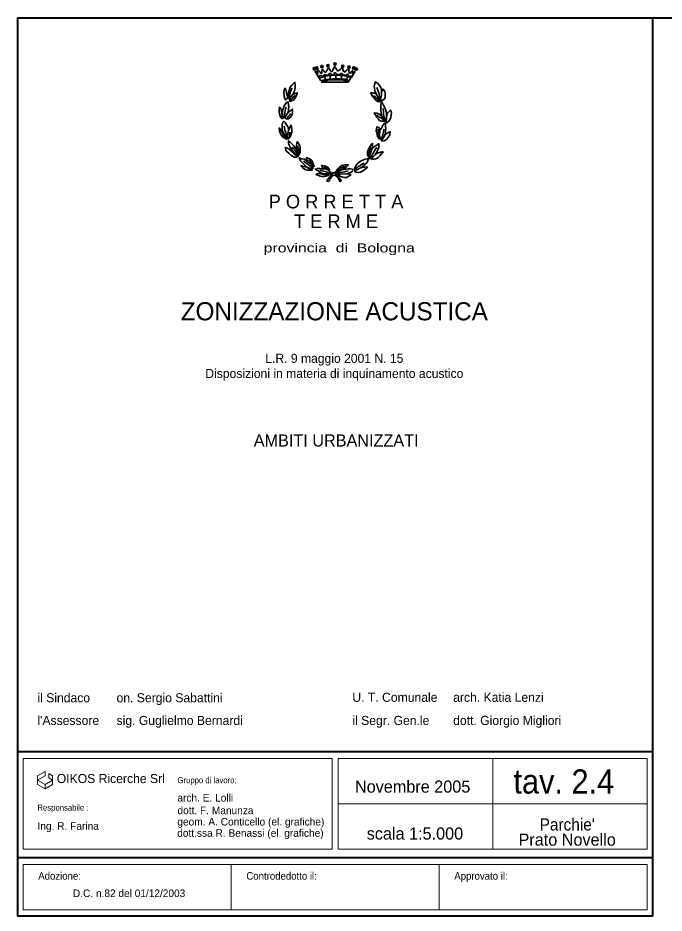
# Model space of a CAD drawing. Extents: x 650071 to 653841, y 889105 to 891996.
# Drawn here: x 650071 to 651141, y 890515 to 891996 of the extents above; entities that cross this region are included whole.
import ezdxf
from ezdxf.enums import TextEntityAlignment as Align

# ---------------------------------------------------------------- set-up
doc = ezdxf.new("R2010")
doc.units = 0
doc.header["$LTSCALE"] = 5.6
doc.layers.add('61', color=7, linetype='Continuous', lineweight=35)

msp = doc.modelspace()

# ---------------------------------------------------------------- hatches: boundary and pattern name
at = {"layer": '61'}
for points in [[(650596.16, 891921.2, 1), (650596.16, 891917.36, 1)], [(650561.94, 891913.61, 1), (650561.94, 891909.77, 1)], [(650566.08, 891914.72, 1), (650566.08, 891910.88, 1)], [(650574.52, 891917.09, 1), (650574.52, 891913.25, 1)], [(650584.49, 891918.36, 1), (650584.49, 891914.51, 1)], [(650608.89, 891917.57, 1), (650608.89, 891913.72, 1)], [(650619.17, 891916.46, 1), (650619.17, 891912.61, 1)], [(650627.3, 891914.72, 1), (650627.3, 891910.88, 1)], [(650631.29, 891913.3, 1), (650631.29, 891909.45, 1)]]:
    msp.add_hatch(color=256, dxfattribs=at).paths.add_polyline_path(points)

# ---------------------------------------------------------------- linework, layer by layer
at = {"layer": '61', "lineweight": 40}
for p, q in [((651121.43, 891995.66), (652174.45, 891995.66)), ((650071.44, 890782.2), (651121.44, 890782.2)), ((650071.44, 890606.7), (651121.44, 890606.7))]:
    msp.add_line(p, q, dxfattribs=at)
at = {"layer": '61'}
for p, q in [((650581.11, 891893.8), (650578.36, 891898.72)), ((650585.86, 891901.37), (650585.86, 891901.25)), ((650588.49, 891894.77), (650587.86, 891900.45)), ((650597.51, 891895.4), (650597.51, 891900.77)), ((650607.06, 891894.92), (650607.21, 891900.77)), ((650615.34, 891893.32), (650616.71, 891898.4)), ((650508.59, 891832.05), (650508.29, 891828.72)), ((650537.44, 891770.77), (650534.84, 891773.15)), ((650534.53, 891766.35), (650537.43, 891770.78)), ((650587.86, 891743.6), (650585.56, 891743.12)), ((650572.98, 891739.49), (650570.21, 891738.53))]:
    msp.add_line(p, q, dxfattribs=at)
at = {"layer": '61', "lineweight": 13}
for p, q in [((650079.96, 890770.65), (650079.96, 890620.22)), ((650079.96, 890770.65), (650591.41, 890770.65)), ((650591.41, 890770.65), (650591.41, 890620.22)), ((650601.44, 890770.65), (650601.44, 890620.22)), ((650601.44, 890770.65), (651112.91, 890770.65)), ((650857.19, 890770.65), (650857.19, 890620.22)), ((651112.91, 890770.65), (651112.91, 890620.22)), ((650601.42, 890695.44), (651112.9, 890695.44)), ((650079.96, 890620.22), (650591.41, 890620.22)), ((650601.44, 890620.22), (651112.91, 890620.22)), ((650079.96, 890595.17), (651112.91, 890595.17)), ((650079.96, 890595.15), (650079.96, 890519.95)), ((650424.26, 890595.15), (650424.26, 890519.95)), ((650768.59, 890595.15), (650768.59, 890519.95)), ((651112.91, 890595.15), (651112.91, 890519.95)), ((650079.96, 890519.95), (651112.91, 890519.95))]:
    msp.add_line(p, q, dxfattribs=at)
at = {"layer": '61', "lineweight": 40}
msp.add_lwpolyline([(651121.44, 891995.65), (651121.44, 890509.4), (650071.44, 890509.4), (650071.44, 891995.65)], close=True, dxfattribs=at)
at = {"layer": '61'}
for points in [[(650585.24, 891913.1), (650584.04, 891911.05), (650581.71, 891906.62), (650580.79, 891905.67), (650579.59, 891905.67), (650578.96, 891906.45), (650578.04, 891907.4), (650577.14, 891908.82), (650574.99, 891910.4), (650574.66, 891907.72), (650574.51, 891905.67), (650574.36, 891904.4), (650572.84, 891904.07), (650571.46, 891906), (650569.44, 891907.87), (650567.31, 891909.8), (650567.49, 891907.25), (650567.76, 891904.72), (650567.61, 891903.3), (650565.16, 891906.92), (650563.76, 891907.87), (650562.54, 891907.72)], [(650562.54, 891907.72), (650567.61, 891899.65), (650569.31, 891896.97), (650570.24, 891897.62), (650570.39, 891898.1), (650570.06, 891899.17), (650570.39, 891899.97), (650570.99, 891900.62), (650572.84, 891900.45), (650573.76, 891899.65), (650574.06, 891898.52), (650577.44, 891899.82), (650577.44, 891900.3), (650577.44, 891900.77), (650577.74, 891901.07), (650578.36, 891901.55), (650578.66, 891901.72), (650579.59, 891901.72), (650580.19, 891901.37), (650580.79, 891900.77), (650585.86, 891901.25)], [(650629.46, 891907.25), (650628.54, 891907.25), (650627.46, 891906.62), (650627.14, 891905.02), (650626.84, 891903.15), (650625.94, 891901.72), (650625.14, 891902.5), (650625.01, 891904.25), (650625.31, 891906.92), (650625.01, 891908.82), (650622.39, 891906), (650621.01, 891904.4), (650620.39, 891904.25), (650619.94, 891904.25), (650619.64, 891905.2), (650619.16, 891907.87), (650619.16, 891910.4), (650617.94, 891911.22), (650615.64, 891909.3), (650613.66, 891907.57), (650612.86, 891906.45), (650611.64, 891906), (650610.59, 891906.77), (650609.79, 891908.67), (650608.59, 891912.32), (650607.36, 891912.95), (650604.59, 891910.4), (650602.29, 891908.52), (650601.06, 891907.87), (650600.29, 891907.87), (650599.06, 891909.8), (650597.51, 891912.62), (650595.84, 891915), (650593.99, 891912.8), (650592.46, 891909.17), (650591.54, 891907.25), (650590.16, 891906.92), (650588.94, 891908.05), (650586.94, 891911.05), (650585.24, 891913.1)], [(650585.86, 891901.37), (650585.86, 891901.87), (650585.86, 891902.5), (650586.16, 891903), (650586.94, 891903.47), (650587.86, 891903.62), (650588.79, 891903.47), (650589.71, 891903), (650589.71, 891901.72), (650594.61, 891901.72), (650594.61, 891902.17), (650594.61, 891903.62), (650594.79, 891904.25), (650595.54, 891904.55), (650596.61, 891904.87), (650597.69, 891904.25), (650598.61, 891903.3), (650598.61, 891902.35), (650605.04, 891901.87), (650605.04, 891902.17), (650605.04, 891902.67), (650605.34, 891903.47), (650605.84, 891903.77), (650606.89, 891903.77), (650607.96, 891903.47), (650608.59, 891902.02), (650614.86, 891900.62), (650614.86, 891901.25), (650615.49, 891902.02), (650616.26, 891902.67), (650617.49, 891902.67), (650617.94, 891901.55), (650617.94, 891899.82), (650621.46, 891898.85), (650621.64, 891899.5), (650622.56, 891899.97), (650623.76, 891898.52), (650623.31, 891897.3), (650626.84, 891902.35), (650629.46, 891907.25)], [(650519.49, 891872.52), (650520.86, 891877.42), (650522.24, 891881.25), (650524.71, 891884.52), (650527.31, 891887.07), (650529.76, 891889), (650530.54, 891885.17), (650530.54, 891880.6), (650529.61, 891876.47), (650528.24, 891872.52), (650526.41, 891868.72), (650528.84, 891870.17), (650533.46, 891871.9), (650533.31, 891870.45), (650532.06, 891866.37), (650530.54, 891863.35), (650527.79, 891860.35), (650524.39, 891858.62), (650521.34, 891857.5), (650520.71, 891861.62)], [(650520.56, 891861.62), (650520.56, 891865.25), (650521.19, 891869.05), (650522.24, 891872.37), (650523.34, 891875.37), (650525.16, 891879.32)], [(650671.19, 891860.12), (650669.66, 891864.32), (650669.04, 891869.22), (650668.14, 891873.02), (650666.91, 891876.02), (650665.51, 891880.6)], [(650520.56, 891861.62), (650519.19, 891864.65), (650518.89, 891868.1), (650519.49, 891872.52)], [(650526.41, 891868.72), (650523.19, 891865.07), (650520.71, 891861.62)], [(650521.34, 891857.5), (650523.64, 891861.15), (650525.31, 891862.55), (650527.31, 891865.25), (650530.06, 891867.47)], [(650664.29, 891869.85), (650666.29, 891865.75), (650668.44, 891862.6), (650669.49, 891860.2), (650670.56, 891858.15), (650667.51, 891859.72), (650665.69, 891861.62), (650663.84, 891863.67), (650661.66, 891866.05), (650660.46, 891867.5)], [(650673.34, 891873.17), (650673.04, 891868.6), (650672.59, 891864.95), (650671.81, 891862.12), (650670.56, 891858.15)], [(650508.29, 891828.72), (650511.36, 891832.05), (650512.61, 891834.72), (650512.89, 891838.85), (650513.96, 891842.32), (650514.44, 891845.17), (650515.19, 891848.02)], [(650517.19, 891836.8), (650515.04, 891833.62), (650513.36, 891830.62)], [(650515.19, 891828.42), (650517.34, 891831.1), (650519.01, 891833), (650521.34, 891835.52), (650522.56, 891837.45)], [(650675.94, 891827.82), (650673.19, 891829.55), (650669.49, 891831.27), (650665.19, 891834.92)], [(650678.39, 891825.1), (650675.94, 891827.82), (650675.16, 891830.17), (650673.49, 891833.35)], [(650682.21, 891821.62), (650679.31, 891826.37), (650677.46, 891831.57), (650676.71, 891836.05), (650676.24, 891840.3), (650675.64, 891845.97)], [(650519.01, 891795.4), (650521.94, 891798.57), (650523.16, 891801.72), (650524.71, 891807.12), (650524.56, 891810.87), (650524.09, 891815.65), (650523.16, 891818.32), (650520.86, 891812.8), (650519.49, 891809.8), (650518.74, 891805.7), (650519.01, 891811.7), (650518.09, 891815.8), (650515.81, 891818.97), (650513.51, 891822.6), (650511.66, 891824.82), (650509.84, 891822.92), (650508.59, 891818.5), (650508.59, 891815.65), (650508.59, 891811.52), (650509.51, 891808.05), (650511.96, 891803.3), (650514.56, 891799.2), (650515.81, 891795.25), (650515.04, 891796.82), (650513.34, 891798.72), (650511.19, 891801.72), (650509.36, 891805.2), (650507.84, 891809), (650503.84, 891813.75), (650504.29, 891808.52), (650505.39, 891805.5), (650506.31, 891802.97), (650508.44, 891800.3), (650510.11, 891798.25), (650512.89, 891796.67), (650515.81, 891795.25), (650519.02, 891795.41)], [(650516.11, 891797.7), (650515.66, 891800.77), (650514.74, 891805.82), (650513.04, 891809.95), (650512.61, 891813.27), (650511.96, 891816.77)], [(650681.46, 891831.27), (650681.16, 891828.57), (650680.84, 891827.17), (650682.21, 891821.62)], [(650518.74, 891805.7), (650517.79, 891801.42), (650517.19, 891798.57), (650515.04, 891796.82)], [(650517.19, 891798.57), (650519.01, 891795.4), (650520.11, 891798.72), (650521.46, 891802.82), (650521.64, 891806.62)], [(650669.44, 891795.72), (650668.89, 891799.52), (650668.14, 891805.05), (650667.51, 891808.67), (650667.51, 891811.37)], [(650670.56, 891809.97), (650670.26, 891806.8), (650669.96, 891803.95), (650669.96, 891801.72), (650670.56, 891798.57)], [(650678.56, 891802.2), (650676.86, 891798.4), (650673.51, 891793.65), (650673.64, 891797.45), (650674.56, 891800.77), (650675.64, 891804.72), (650676.41, 891807.9), (650677.31, 891811.7)], [(650537.44, 891770.77), (650538.49, 891772.97), (650538.79, 891775.17), (650538.79, 891777.7), (650538.66, 891780.87), (650538.19, 891784.05), (650537.11, 891786.25), (650535.26, 891788.77), (650533.59, 891791.15), (650532.81, 891788.77), (650532.51, 891784.52), (650532.39, 891781.85), (650532.81, 891778.02), (650530.21, 891780.42), (650528.06, 891784.2), (650525.16, 891787.05), (650521.79, 891789.9), (650519.01, 891792.12), (650519.01, 891790.52), (650519.19, 891788.15), (650520.39, 891785), (650522.09, 891781.67), (650523.94, 891778.35), (650526.21, 891775.02), (650528.39, 891772.32), (650531.89, 891769.65), (650534.51, 891766.35), (650533.59, 891767.45), (650530.36, 891769), (650527.44, 891771.25), (650525.16, 891773.77), (650522.86, 891775.97), (650520.71, 891778.35), (650517.01, 891780.07), (650513.81, 891781.05), (650514.89, 891776.92), (650516.71, 891774.4), (650520.11, 891771.4), (650522.86, 891768.55), (650525.76, 891766.65)], [(650532.81, 891778.02), (650534.84, 891773.15), (650534.84, 891769), (650533.59, 891767.45), (650532.99, 891772.32), (650530.96, 891775.17), (650528.99, 891777.55), (650526.84, 891779.77), (650525.49, 891781.67)], [(650537.44, 891770.77), (650535.89, 891774.7), (650535.59, 891779), (650534.84, 891783.9)], [(650653.56, 891764.42), (650651.71, 891769.17), (650652.81, 891772.65), (650653.89, 891778.52), (650655.24, 891780.72), (650656.01, 891782)], [(650658.16, 891780.42), (650657.09, 891778.52), (650656.16, 891775.17), (650655.56, 891773.77), (650654.49, 891770.12), (650653.56, 891767.27), (650653.56, 891764.42)], [(650654.34, 891762.87), (650656.46, 891766.5), (650658.61, 891770.77), (650661.39, 891775.67), (650663.84, 891779.62), (650666.16, 891780.72)], [(650525.76, 891766.65), (650528.84, 891765.52), (650532.06, 891765.37), (650534.51, 891766.35)], [(650559.99, 891746.42), (650557.21, 891748.95), (650554.76, 891750.82), (650552.46, 891752.45), (650550.31, 891754.17), (650548.01, 891755.9), (650546.01, 891757), (650544.16, 891758.42)], [(650561.81, 891749.27), (650561.21, 891751.62), (650560.29, 891753.85), (650559.36, 891756.37), (650558.29, 891758.62), (650557.04, 891760.5), (650555.21, 891762.07), (650551.99, 891763.35), (650549.09, 891764.45), (650549.24, 891763.5), (650549.84, 891760.97), (650550.46, 891758.3)], [(650550.47, 891758.31), (650556.61, 891752.91), (650557.45, 891751.73), (650559.98, 891750.71), (650561.82, 891749.28)], [(650561.81, 891749.27), (650558.89, 891753.07), (650556.91, 891755.6), (650555.21, 891758.42), (650553.69, 891760.02), (650552.59, 891760.5)], [(650654.34, 891762.87), (650657.54, 891764.75), (650660.01, 891766.35)], [(650561.81, 891749.27), (650559.99, 891750.7), (650557.46, 891751.72)], [(650589.71, 891740.1), (650586.79, 891742.17), (650584.34, 891744.05), (650580.79, 891745.32), (650577.59, 891745.8), (650574.21, 891746.12), (650570.84, 891746.42), (650567.61, 891746.25), (650564.71, 891745.65), (650563.46, 891745.5), (650564.86, 891744.22), (650566.99, 891743.42), (650568.69, 891742.62), (650570.99, 891740.87), (650572.96, 891739.47)], [(650589.71, 891740.1), (650585.86, 891739.77), (650583.56, 891739.97), (650581.44, 891740.87), (650579.11, 891741.7), (650576.51, 891742.17), (650574.06, 891743.12), (650571.46, 891743.25)], [(650587.86, 891743.6), (650586.04, 891746.12), (650583.89, 891748.65), (650581.44, 891750.07), (650578.04, 891750.85), (650574.81, 891751.65), (650573.89, 891751.95), (650574.66, 891750.22), (650576.21, 891747.7), (650578.04, 891747.22), (650580.04, 891747.07), (650582.56, 891744.7)], [(650586.74, 891743.35), (650583.74, 891746.42), (650581.11, 891748.17), (650578.04, 891749.75)], [(650582.56, 891744.71), (650584.35, 891744.07), (650585.57, 891743.12), (650587.86, 891743.61)], [(650596.46, 891738.67), (650601.21, 891742.8), (650603.81, 891745.15), (650606.89, 891747.37), (650610.41, 891749.27), (650613.66, 891749.75)], [(650596.76, 891735.5), (650601.39, 891738.85), (650604.74, 891739.77), (650609.19, 891740.4), (650612.14, 891741.2), (650615.94, 891742.17), (650617.79, 891742.5)], [(650607.36, 891744.05), (650604.59, 891743.12), (650602.44, 891741.52), (650600.14, 891739.97), (650599.06, 891738.35), (650596.91, 891736.77)], [(650628.29, 891745.15), (650631.99, 891747.2), (650634.56, 891749.72), (650637.49, 891750.7), (650639.94, 891753.22), (650644.26, 891755.12)], [(650639.11, 891747.57), (650636.26, 891746.42), (650634.44, 891745.3), (650632.41, 891744.35), (650631.19, 891743.57), (650630.29, 891742.92), (650629.21, 891742)], [(650570.21, 891738.52), (650568.21, 891738.05), (650566.09, 891736.95), (650564.86, 891736.62), (650566.99, 891735.67), (650569.44, 891734.72), (650571.76, 891733.95), (650574.51, 891733.47), (650576.66, 891733.3), (650578.81, 891733.47), (650581.29, 891733.95), (650584.19, 891734.72), (650586.94, 891736), (650582.34, 891737.87), (650584.49, 891738.05), (650588.01, 891738.35), (650589.71, 891740.1)], [(650570.21, 891738.52), (650572.66, 891737.57), (650574.99, 891737.1), (650577.44, 891736.47), (650580.64, 891736.15), (650584.04, 891736.15), (650586.94, 891736)], [(650582.34, 891737.87), (650578.51, 891737.87), (650575.44, 891738.35), (650572.96, 891739.47)], [(650593.56, 891739.77), (650592.64, 891738.35), (650591.84, 891737.1), (650591.54, 891734.87)], [(650596.76, 891735.5), (650601.99, 891736.77), (650607.36, 891737.42), (650612.74, 891737.1), (650615.49, 891737.72)]]:
    msp.add_lwpolyline(points, dxfattribs=at)
for points in [[(650572.84, 891891.6), (650570.24, 891895.85), (650573.76, 891897.12), (650578.36, 891898.72), (650584.19, 891899.82), (650591.09, 891900.62), (650598.31, 891900.77), (650604.44, 891900.62), (650609.36, 891900.3), (650613.96, 891899.35), (650618.26, 891897.92), (650622.56, 891896.32), (650619.16, 891890.95), (650617.31, 891892.85), (650612.74, 891894.12), (650604.31, 891894.92), (650599.21, 891895.4), (650593.06, 891894.92), (650586.16, 891894.27), (650581.11, 891893.8), (650576.51, 891892.7)], [(650577.89, 891890.95), (650584.81, 891892.4), (650591.09, 891893), (650597.51, 891893.47), (650602.59, 891893.32), (650609.96, 891892.55), (650615.34, 891891.75), (650618.16, 891889.6), (650574.29, 891889.3)], [(650514.56, 891877.42), (650515.36, 891875.22), (650516.11, 891871.57), (650517.04, 891867.8), (650517.34, 891864.92), (650516.86, 891862.1), (650514.44, 891860.02), (650513.36, 891862.4), (650512.29, 891865.57), (650511.79, 891868.4), (650511.51, 891872.05), (650511.79, 891875.85), (650512.89, 891879), (650513.36, 891879.65)], [(650669.36, 891856.72), (650670.56, 891858.15), (650675.19, 891859.57), (650677.16, 891860.5), (650679.04, 891863.52), (650679.19, 891866.67), (650679.19, 891871.42), (650678.39, 891873.35), (650677.34, 891876.32), (650675.19, 891878.07), (650674.74, 891876.2), (650673.34, 891873.17), (650673.04, 891876.32), (650671.81, 891880.6), (650669.66, 891884.1), (650667.51, 891886.45), (650663.36, 891889.95), (650662.59, 891888.82), (650661.36, 891885.2), (650661.24, 891882.82), (650661.36, 891879.5), (650661.99, 891876.32), (650662.76, 891873.67), (650664.29, 891869.85), (650661.06, 891871.42), (650657.86, 891871.57), (650655.39, 891871.75), (650657.39, 891867.65), (650659.39, 891864.47), (650661.36, 891862.12), (650663.84, 891859.72), (650666.61, 891857.52)], [(650508.29, 891828.72), (650505.69, 891833.15), (650504.59, 891836.95), (650503.69, 891840.6), (650503.69, 891844.37), (650504.59, 891848.02), (650507.51, 891843.9), (650507.84, 891841.37), (650507.99, 891836.95), (650508.59, 891832.05), (650509.21, 891836.47), (650509.21, 891839.65), (650509.96, 891844.37), (650510.76, 891846.27), (650511.66, 891848.82), (650512.89, 891851.67), (650514.29, 891853.57), (650516.56, 891856.1), (650518.26, 891856.87), (650519.01, 891852.92), (650519.64, 891848.17), (650519.19, 891844.05), (650518.41, 891839.97), (650517.19, 891836.8), (650519.34, 891839), (650521.64, 891841.52), (650524.56, 891843.6), (650525.64, 891844.87), (650525.64, 891841.22), (650525.64, 891837.75), (650525.01, 891835.2), (650523.46, 891833), (650521.49, 891830.45), (650519.49, 891828.9), (650517.19, 891828.42), (650515.19, 891828.42), (650513.36, 891830.62)], [(650678.39, 891825.1), (650673.64, 891824.97), (650670.09, 891826.2), (650667.64, 891828.57), (650665.64, 891830.65), (650664.11, 891833.5), (650661.96, 891836.82), (650661.04, 891838.87), (650665.34, 891838.25), (650668.89, 891836.97), (650673.49, 891833.35), (650672.69, 891837.92), (650671.94, 891842.35), (650671.79, 891845.52), (650671.79, 891852.65), (650672.86, 891858.17), (650674.71, 891854.52), (650677.16, 891850.1), (650679.46, 891845.82), (650681.46, 891839.17), (650681.46, 891831.27), (650682.06, 891833.5), (650682.69, 891837.45), (650685.14, 891840.45), (650686.81, 891842.02), (650688.06, 891843.15), (650688.99, 891840.92), (650689.44, 891838.07), (650689.29, 891835.07), (650688.51, 891830.97), (650686.81, 891827.17), (650684.54, 891824.17), (650682.21, 891821.62)], [(650670.41, 891794.27), (650668.44, 891797.15), (650666.74, 891799.05), (650665.69, 891802.05), (650665.19, 891805.82), (650664.44, 891808.05), (650664.74, 891812.65), (650665.36, 891815.17), (650668.14, 891814.7), (650669.81, 891812.65), (650670.56, 891809.97), (650672.86, 891813.27), (650675.64, 891818.5), (650678.09, 891821.5), (650679.49, 891820.72), (650679.79, 891817.37), (650680.41, 891812.32), (650679.79, 891806.62), (650678.56, 891802.2), (650683.61, 891805.35), (650686.69, 891807.12), (650687.74, 891807.42), (650687.14, 891802.2), (650684.36, 891797.77), (650681.16, 891794.45), (650677.64, 891792.55), (650673.34, 891791.75), (650673.51, 891793.65), (650670.56, 891798.57), (650670.56, 891795.07)], [(650653.56, 891764.42), (650650.79, 891767.12), (650650.19, 891769.82), (650650.19, 891774.25), (650651.11, 891777.1), (650652.81, 891780.9), (650654.79, 891784.05), (650656.79, 891786.57), (650658.01, 891788.35), (650658.16, 891785.8), (650658.16, 891782.95), (650658.16, 891780.42), (650660.94, 891782.62), (650664.29, 891784.7), (650666.01, 891785.62), (650667.99, 891787.37), (650669.06, 891787.22), (650668.91, 891784.37), (650668.61, 891781.2), (650666.91, 891777.4), (650666.76, 891775.5), (650664.46, 891772.02), (650662.46, 891769.35), (650659.99, 891766.32), (650665.36, 891771.55), (650667.69, 891772.65), (650671.36, 891773.62), (650673.81, 891774.07), (650675.66, 891774.07), (650674.89, 891772.65), (650672.74, 891770.6), (650671.06, 891768.07), (650669.21, 891766.35), (650667.06, 891763.95), (650663.99, 891762.7), (650660.76, 891761.9), (650657.54, 891761.75), (650654.34, 891762.87)], [(650559.36, 891747.85), (650558.29, 891750.55), (650556.61, 891752.9), (650554.29, 891755.12), (650551.84, 891757.17), (650549.09, 891759.37), (650545.39, 891761.9), (650541.11, 891762.25), (650538.36, 891763.5), (650536.96, 891764.3), (650537.86, 891761.45), (650539.71, 891758.75), (650541.86, 891756.22), (650543.86, 891754), (650546.19, 891752.12), (650549.84, 891748.47), (650544.94, 891749.9), (650540.49, 891750.82), (650539.89, 891751), (650542.49, 891748.3), (650545.39, 891745.95), (650547.86, 891744.52), (650550.91, 891743.72), (650555.21, 891743.42), (650558.46, 891743.57), (650552.76, 891745.95), (650549.84, 891748.47), (650553.84, 891746.9), (650557.04, 891746.57), (650559.99, 891746.42)], [(650628.29, 891745.15), (650629.36, 891748.8), (650631.04, 891751.62), (650633.04, 891754.32), (650635.79, 891756.52), (650638.56, 891758.42), (650641.34, 891759.85), (650644.26, 891761.57), (650647.16, 891762.22), (650651.59, 891763.02), (650652.21, 891762.87), (650650.69, 891759.85), (650650.09, 891758.12), (650648.69, 891756.05), (650647.31, 891754.65), (650645.61, 891752.6), (650643.94, 891751.47), (650639.11, 891747.55), (650642.86, 891748.62), (650645.79, 891748.95), (650649.31, 891749.1), (650649.61, 891747.97), (650645.79, 891744.67), (650641.49, 891742), (650638.41, 891740.4), (650634.44, 891739.92), (650630.29, 891740.57), (650629.21, 891742)], [(650596.46, 891738.67), (650598.44, 891742.5), (650600.89, 891745.8), (650603.21, 891748.02), (650605.51, 891750.07), (650607.66, 891751.47), (650610.41, 891751.95), (650613.49, 891752.6), (650616.26, 891752.75), (650618.41, 891752.6), (650617.79, 891751.95), (650616.39, 891750.55), (650614.71, 891748.65), (650611.64, 891746.9), (650607.36, 891744.05), (650610.11, 891744.85), (650613.96, 891745.5), (650617.79, 891745.95), (650621.31, 891745.95), (650625.14, 891745.65), (650625.94, 891744.05), (650625.14, 891742.17), (650622.69, 891740.57), (650620.24, 891739.32), (650615.49, 891737.72), (650620.56, 891737.42), (650622.39, 891735.82), (650619.31, 891733.77), (650615.34, 891731.42), (650611.96, 891731.42), (650608.89, 891732.05), (650605.99, 891733.15), (650603.51, 891734.25), (650601.81, 891735.5), (650596.76, 891735.5), (650596.91, 891736.77)], [(650593.56, 891739.77), (650594.91, 891740.1), (650596.46, 891738.67), (650596.91, 891736.77), (650596.76, 891735.5), (650593.71, 891735.2), (650591.54, 891734.87), (650589.86, 891731.1), (650587.86, 891729.2), (650586.49, 891726.35), (650584.94, 891724.92), (650582.64, 891725.87), (650583.11, 891727.92), (650584.94, 891729.32), (650586.49, 891731.42), (650589.11, 891733.77), (650591.54, 891734.87), (650589.54, 891735.67), (650589.41, 891737.25), (650591.24, 891739.47)], [(650596.76, 891735.5), (650602.59, 891731.72), (650604.11, 891729.65), (650606.59, 891727.12), (650605.66, 891725.4), (650604.44, 891724.92), (650603.06, 891727.6), (650601.21, 891730.3), (650599.54, 891732.52), (650597.84, 891734.07)]]:
    msp.add_lwpolyline(points, close=True, dxfattribs=at)
at = {"layer": '61', "lineweight": 13}
for points in [[(650116.34, 890749.1), (650103.93, 890741.97), (650103.93, 890734.8), (650116.34, 890741.97)], [(650128.75, 890741.97), (650122.55, 890745.53), (650122.55, 890738.38), (650128.75, 890734.8)], [(650116.34, 890727.64), (650103.93, 890734.8), (650103.93, 890727.64), (650116.34, 890720.5)], [(650128.75, 890734.8), (650116.34, 890727.64), (650116.34, 890720.5), (650128.75, 890727.64)]]:
    msp.add_lwpolyline(points, close=True, dxfattribs=at)
at = {"layer": '61'}
for centre in [(650596.16, 891919.28), (650561.94, 891911.69), (650566.08, 891912.8), (650574.52, 891915.17), (650584.49, 891916.44), (650608.89, 891915.65), (650619.17, 891914.54), (650627.3, 891912.8), (650631.29, 891911.37)]:
    msp.add_circle(centre, 1.92, dxfattribs=at)

# ---------------------------------------------------------------- texts
for s, height, p in [('P O R R E T T A', 22.56, (650597.9, 891680.58)), ('T E R M E', 22.56, (650597.9, 891647.98)), ('ZONIZZAZIONE ACUSTICA', 30, (650595.05, 891495.33)), ('L.R. 9 maggio 2001 N. 15', 15, (650595.1, 891424.98)), ('Disposizioni in materia di inquinamento acustico', 15, (650595.09, 891399.98)), ('AMBITI URBANIZZATI', 20.06, (650598.1, 891286.57)), ('Novembre 2005', 20.06, (650724.67, 890713.95)), ('Prato Novello', 20.06, (650980.4, 890626.22))]:
    msp.add_text(s, height=height, dxfattribs=at).set_placement(p, align=Align.CENTER)
for s, height, width, p in [('provincia  di  Bologna', 15.04, 1.3, (650603.15, 891607.68)), ("Parchie'", 20.06, 0.95, (650980.4, 890651.27))]:
    msp.add_text(s, height=height, dxfattribs=dict(at, width=width)).set_placement(p, align=Align.CENTER)
for s, height, p in [('il Sindaco', 15.04, (650103.72, 890863.4)), ('on. Sergio Sabattini', 15.04, (650234.65, 890863.4)), ('U. T. Comunale', 15.04, (650624.9, 890864.2)), ('arch. Katia Lenzi', 15.04, (650791.73, 890864.2)), ("l'Assessore", 15.04, (650103.75, 890825.88)), ('sig. Guglielmo Bernardi', 15.04, (650234.68, 890825.88)), ('il Segr. Gen.le', 15.04, (650624.9, 890825.88)), ('dott. Giorgio Migliori', 15.04, (650791.73, 890825.88)), ('OIKOS Ricerche Srl', 15.04, (650135.77, 890729.78)), ('arch. E. Lolli', 12.54, (650335.35, 890699.18)), ('dott. F. Manunza', 12.54, (650335.52, 890678.3)), ('Ing. R. Farina', 12.54, (650103.87, 890652.55)), ('geom. A. Conticello (el. grafiche)', 12.54, (650335.3, 890659.6)), ('dott.ssa R. Benassi (el. grafiche)', 12.54, (650335.07, 890640.9)), ('scala 1:5.000     ', 20.06, (650648.67, 890636.33)), ('D.C. n.82 del 01/12/2003', 12.5, (650162.55, 890541.24))]:
    msp.add_text(s, height=height, dxfattribs=at).set_placement(p)
at = {"layer": '61', "width": 0.95}
for s, height, p in [('tav. 2.4', 40, (650891.52, 890712.45)), ('Gruppo di lavoro:', 10.03, (650335.57, 890729.6)), ('Responsabile :', 10.03, (650103.85, 890684.25)), ('Adozione:', 12.5, (650105.17, 890569.95)), ('Controdedotto il:', 12.5, (650449.55, 890569.95)), ('Approvato il:', 12.5, (650793.62, 890569.95))]:
    msp.add_text(s, height=height, dxfattribs=at).set_placement(p)

doc.saveas('drawing.dxf')
